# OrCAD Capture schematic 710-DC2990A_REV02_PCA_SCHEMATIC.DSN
size B; title: 5V, 3A SYNCHRONOUS STEP-DOWN SILENT SWITCHER; rev: 01
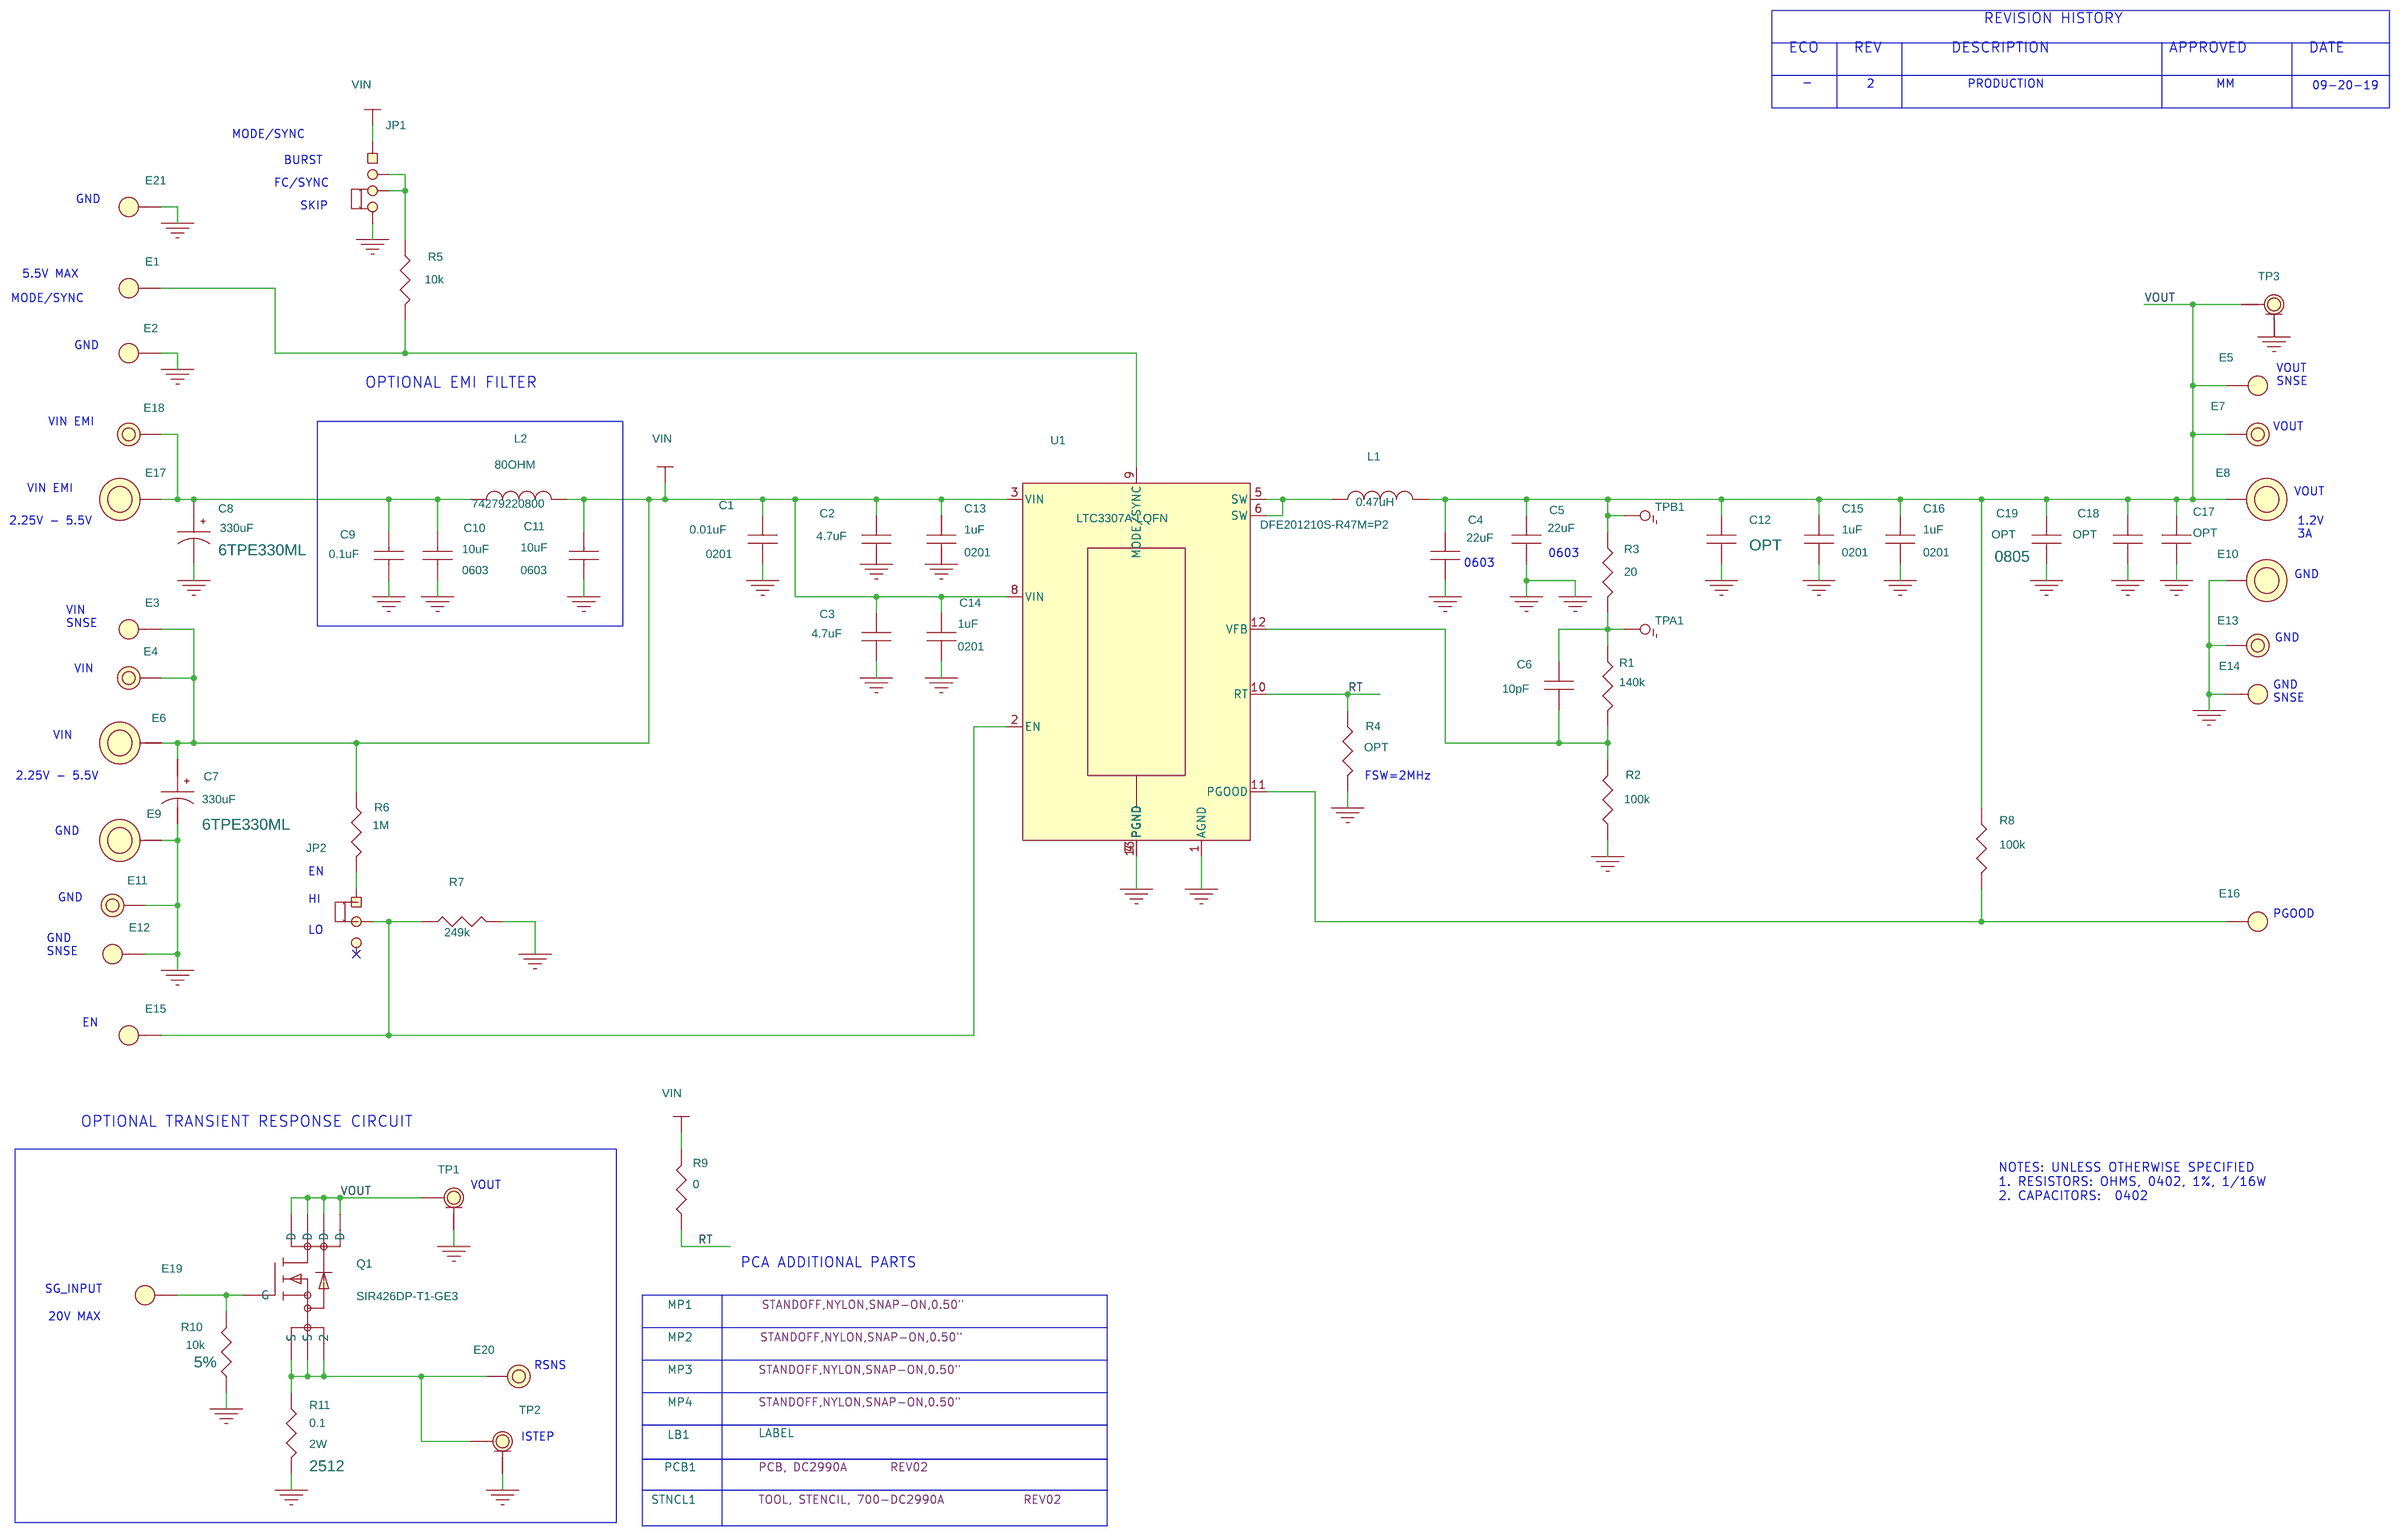
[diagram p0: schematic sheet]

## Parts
C1  0.01uF  [CC0201M]
C2  4.7uF  [CC0402N]
C3  4.7uF  [CC0402N]
C4  22uF  [CC0603N]
C5  22uF  [CC0603N]
C6  10pF  [CC0402N]
C7  330uF  [CAPMP7343N]
C8  330uF  [CAPMP7343N]
C9  0.1uF  [CC0402N]
C10  10uF  [CC0603N]
C11  10uF  [CC0603N]
C12  0.1uF  [CC0402N]
C13  1uF  [CC0201M]
C14  1uF  [CC0201M]
C15  1uF  [CC0201M]
C16  1uF  [CC0201M]
C17  OPT  [CC0402N]
C18  OPT  [CC0805N]
C19  OPT  [CC0805N]
E1  TEST POINT  [MILLMAX2308]
E2  TEST POINT  [MILLMAX2308]
E3  TEST POINT  [MILLMAX2308]
E4  TEST POINT  [MILLMAX2501]
E5  TEST POINT  [MILLMAX2308]
E6  BANANA JACK  [KEY-575-4]
E7  TEST POINT  [MILLMAX2501]
E8  BANANA JACK  [KEY-575-4]
E9  BANANA JACK  [KEY-575-4]
E10  BANANA JACK  [KEY-575-4]
E11  TEST POINT  [MILLMAX2501]
E12  TEST POINT  [MILLMAX2308]
E13  TEST POINT  [MILLMAX2501]
E14  TEST POINT  [MILLMAX2308]
E15  TEST POINT  [MILLMAX2308]
E16  TEST POINT  [MILLMAX2308]
E17  BANANA JACK  [KEY-575-4]
E18  TEST POINT  [MILLMAX2501]
E19  TEST POINT  [MILLMAX2308]
E20  TEST POINT  [MILLMAX2501]
E21  TEST POINT  [MILLMAX2308]
JP1  HDR  [JP4X1/079]
JP2  HDR  [HD1X3-079]
L1  0.47uH  [MURATA-DFE201210S]
L2  80OHM  [WURTH-0805]
LB1  LABEL  [895-0154_REV01]
MP1  STANDOFF  [KEYSTONE_8829-8834]
MP2  STANDOFF  [KEYSTONE_8829-8834]
MP3  STANDOFF  [KEYSTONE_8829-8834]
MP4  STANDOFF  [KEYSTONE_8829-8834]
PCB1  PCB, DC2990A
Q1  SIR426DP-T1-GE3  [VISHAY_PPAK_SO-8]
R1  140k  [CR0402N]
R2  100k  [CR0402N]
R3  20  [CR0402N]
R4  OPT  [CR0402N]
R5  10k  [CR0402N]
R6  1M  [CR0402N]
R7  249k  [CR0402N]
R8  100k  [CR0402N]
R9  0  [CR0402N]
R10  10k  [CR0402N]
R11  0.1  [CR2512N]
STNCL1  TOOL, STENCIL, 700-DC2990A
TP1  U.FL  [HIROSE-FL-R-SMT-1]
TP2  TEST JACK  [HODEN-PA-652_ALT1]
TP3  U.FL  [HIROSE-FL-R-SMT-1]
TPA1  COPPER FEATURE PAD  [PADSTYLE1]
TPB1  COPPER FEATURE PAD  [PADSTYLE1]
U1  LTC3307A-LQFN  [LTC-LQFN-12-1530]
XJP1  SHUNT
XJP2  SHUNT

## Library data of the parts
C1 = CAP: CAP.,0.01uF,X7R,10V,10%,0201; CLASS: DISCRETE; Dielectric Type: X7R; FPLIST: CC0201N,CC0201L,CC0201M; Inventory Qty: 28511; Manufacturer: MURATA; Manufacturer PN: GRM033R70J103KA01D; PART_NUMBER: 150-0377; Package Size: 0201; Rated Voltage: 10V; Tolerance: 10%
C2 C3 = CAP: CAP.,4.7uF,X6S,6.3V,20%,0402; CLASS: DISCRETE; Dielectric Type: X6S; FPLIST: CC0402N, CC0402M,CC0402L; Inventory Qty: 0; Manufacturer: MURATA; Manufacturer PN: GRM155C80J475MEAAD; PART_NUMBER: 150-0793; Package Size: 0402; Rated Voltage: 6.3V; Temperature Coefficient: X6S; Tolerance: 20%
C4 C5 = CAP: CAP.,22uF,X6S,6.3V,20%,0603; CLASS: DISCRETE; Dielectric Type: X6S; FPLIST: CC0603N,CC0603L,CC0603M; Inventory Qty: 0; Manufacturer: MURATA; Manufacturer PN: GRM188C80J226ME15D; PART_NUMBER: 150-0784; Package Size: 0603; Rated Voltage: 6.3V; Temperature Coefficient: X6S; Tolerance: 20%
C6 = CAP: CAP.,10pF,C0G,50V,5%,0402,AEC-Q200; CLASS: DISCRETE; Dielectric Type: C0G; FPLIST: CC0402N,CC0402L,CC0402M; Inventory Qty: 23844; Manufacturer: MURATA; Manufacturer PN: GCM1555C1H100JA16D; PART_NUMBER: 150-1207; Package Size: 0402; Rated Voltage: 50V; Temperature Coefficient: C0G, NP0; Tolerance: 5%
C7 C8 = CAP_P_ALT: CAP.,330uF,TANT. POSCAP,6.3V,20%,7343,25mOHMS, TPE, NO SUBS. ALLOWED; CLASS: DISCRETE; Dielectric Type: TANT. POSCAP; Inventory Qty: 2150; Manufacturer: PANASONIC; Manufacturer PN: 6TPE330ML; PART_NUMBER: 150-0529; Package Size: 7343; Rated Voltage: 6.3V; Tolerance: 20%; UserField01: 2400mAms, 25mOHMS
C9 = CAP: CAP.,0.1uF,X7R,16V,10%,0402,AEC-Q200; CLASS: DISCRETE; Dielectric Type: X7R; FPLIST: CC0402N,CC0402L,CC0402M; Inventory Qty: 23683; Manufacturer: MURATA; Manufacturer PN: GCM155R71C104KA55D; PART_NUMBER: 150-0506; Package Size: 0402; Rated Voltage: 16V; Tolerance: 10%
C10 C11 = CAP: CAP.,10uF,X7S,6.3V,20%,0603; CLASS: DISCRETE; Dielectric Type: X7S; FPLIST: CC0603N,CC0603L,CC0603M; Inventory Qty: 10800; Manufacturer: TDK; Manufacturer PN: C1608X7S0J106M080AC; PART_NUMBER: 150-1745; Package Size: 0603; Rated Voltage: 6.3V; Tolerance: 20%
C12 = CAP: CAP.,0.1uF,X5R,25V,10%,0402; BOM Notes: OPT; CLASS: DISCRETE; Dielectric Type: X5R; FPLIST: CC0402N,CC0402L,CC0402M; Inventory Qty: 71484; Manufacturer: AVX; Manufacturer PN: 04023D104KAT2A; PART_NUMBER: 150-0249; Package Size: 0402; Rated Voltage: 25V; Tolerance: 10%
C13-C16 = CAP: CAP.,1uF,X7T,6.3V,20%,0201; CLASS: DISCRETE; Dielectric Type: X7T; FPLIST: CC0201N,CC0201L,CC0201M; Inventory Qty: 600; Manufacturer: MURATA; Manufacturer PN: GRM033D70J105ME01D; PART_NUMBER: 150-1771; Package Size: 0201; Rated Voltage: 6.3V; Tolerance: 20%
C17 = CAP: CAP., OPTION, 0402; CLASS: DISCRETE; FPLIST: CC0402N,CC0402L,CC0402M; PART_NUMBER: 150-3148; Package Size: 0402; Package Type: SMD
C18 C19 = CAP: CAP., OPTION, 0805; CLASS: DISCRETE; FPLIST: CC0805N,CC0805L,CC0805M; PART_NUMBER: 150-3036; Package Size: 0805; Package Type: SMD
E1-E3 E5 E12 E14-E16 E19 E21 = TEST_POINT_.156_MILL-MAX_2308: TEST POINT,TURRET,0.064" MTG. HOLE,PCB 0.062" THK; CLASS: IO; Inventory Qty: 760562; Manufacturer PN: 2308-2-00-80-00-00-07-0; PART_NUMBER: 260-0004
E4 E7 E11 E13 E18 E20 = TESTPOINT_.219_MILL-MAX_2501: TEST POINT,TURRET,0.094" MTG. HOLE,PCB 0.062" THK; CLASS: IO; Inventory Qty: 452838; Manufacturer: MILL-MAX; Manufacturer PN: 2501-2-00-80-00-00-07-0; PART_NUMBER: 260-0003
E6 E8-E10 E17 = BANANA_KEYSTONE-575-4: CONN.,BANANA JACK,FEMALE,THT,NON-INSULATED,SWAGE,0.218"; CLASS: IO; Inventory Qty: 194619; Manufacturer: KEYSTONE; Manufacturer PN: 575-4; PART_NUMBER: 250-0428
JP1 = HD1X4-079_ALT: CONN.,HDR,MALE,1x4,2mm,VERT,ST,THT; CLASS: IO; Inventory Qty: 10969; Manufacturer: WURTH ELEKTRONIK; Manufacturer PN: 62000411121; PART_NUMBER: 250-0563
JP2 = 3_PIN_HEADER_.079_SINGLE_ROW_D: CONN.,HDR,MALE,1x3,2mm,VERT,ST,THT; CLASS: IO; Inventory Qty: 26164; Manufacturer: Wurth Elektronik; Manufacturer PN: 62000311121; PART_NUMBER: 250-0484
L1 = IND_ALT: IND.,0.47uH,POWER,20%,3.4A,0.032OHMS,0805; CLASS: DISCRETE; Inventory Qty: 0; Manufacturer: MURATA; Manufacturer PN: DFE201210S-R47M=P2; PART_NUMBER: 200-0784; Package Size: 0805; Tolerance: 20%
L2 = IND_ALT: IND.,80OHM,FERRITE BEAD,25%,4A,0.018OHM,0805,100MHz; CLASS: DISCRETE; Inventory Qty: 0; Manufacturer: WURTH ELEKTRONIK; Manufacturer PN: 74279220800; PART_NUMBER: 200-0765; Package Size: 0805; Tolerance: 25%
LB1 = BLANK_LABEL: LABEL SPEC, DEMO BOARD SERIAL NUMBER; Inventory Qty: 0; Manufacturer: BRADY; Manufacturer PN: THT-96-717-10; PART_NUMBER: 895-0154
MP1-MP4 = BLANK_MECHANICAL_PART: STANDOFF,NYLON,SNAP-ON,0.50"; CLASS: DISCRETE; FPLIST: KEYSTONE_8829-8834,MTG-8831; Inventory Qty: 10977; Manufacturer: WURTH ELEKTRONIK; Manufacturer PN: 702935000; PART_NUMBER: 763-0020
PCB1 = BLANK_PCB_PART: BOM Notes: REV02; CLASS: DISCRETE; Inventory Qty: 0; Manufacturer: MAO BANG; Manufacturer PN: 600-DC2990A; PART_NUMBER: 600-DC2990A
Q1 = 8P_N-CH_TYPE1A: XSTR.,MOSFET,N-CH,40V,15.9A,PPAK SO-8; CLASS: DISCRETE; Inventory Qty: 14900; Manufacturer: VISHAY; PART_NUMBER: 240-0378; Package Size: PowerPAK® SO-8; Package Type: PPAK SO-8; Polarity: MOSFET N-Channel; Rated Power: 41.7W; Rated Voltage: 40V
R1 = RES: RES.,140k OHMS,1%,1/16W,0402,AEC-Q200; CLASS: DISCRETE; FPLIST: CR0402N,CR0402L,CR0402M; Inventory Qty: 72990; Manufacturer: NIC; Manufacturer PN: NRC04F1403TRF; PART_NUMBER: 100-2880; Package Size: 0402; Rated Power: 1/16W; Temperature Coefficient: 100ppm; Tolerance: 1%
R2 = RES: RES.,100k OHMS,1%,1/16W,0402,AEC-Q200; CLASS: DISCRETE; FPLIST: CR0402N,CR0402L,CR0402M; Inventory Qty: 136714; Manufacturer: VISHAY; Manufacturer PN: CRCW0402100KFKED; PART_NUMBER: 100-2396; Package Size: 0402; Rated Power: 1/16W; Temperature Coefficient: 100ppm; Tolerance: 1%
R3 = RES: RES.,20 OHMS,1%,1/16W,0402,AEC-Q200; CLASS: DISCRETE; FPLIST: CR0402N,CR0402L,CR0402M; Inventory Qty: 33808; Manufacturer: NIC; Manufacturer PN: NRC04F20R0TRF; PART_NUMBER: 100-0250; Package Size: 0402; Rated Power: 1/16W; Temperature Coefficient: 100ppm; Tolerance: 1%
R4 = RES: RES., OPTION, 0402; CLASS: DISCRETE; FPLIST: CR0402N,CR0402L,CR0402M; PART_NUMBER: 100-0357; Package Size: 0402
R5 = RES: RES.,10k OHMS,5%,1/16W,0402,AEC-Q200; CLASS: DISCRETE; FPLIST: CR0402N,CR0402L,CR0402M; Inventory Qty: 71445; Manufacturer: NIC; Manufacturer PN: NRC04J103TRF; PART_NUMBER: 100-0214; Package Size: 0402; Rated Power: 1/16W; Temperature Coefficient: 200ppm; Tolerance: 5%
R6 = RES: RES.,1M OHMS,1%,1/16W,0402,AEC-Q200; CLASS: DISCRETE; FPLIST: CR0402N,CR0402L,CR0402M; Inventory Qty: 92093; Manufacturer: STACKPOLE ELECTRONICS, INC.; Manufacturer PN: RMCF0402FT1M00; PART_NUMBER: 100-2457; Package Size: 0402; Rated Power: 1/16W; Temperature Coefficient: 100ppm; Tolerance: 1%
R7 = RES: RES.,249k OHMS,1%,1/16W,0402,AEC-Q200; CLASS: DISCRETE; FPLIST: CR0402N,CR0402L,CR0402M; Inventory Qty: 29476; Manufacturer: NIC; Manufacturer PN: NRC04F2493TRF; PART_NUMBER: 100-2663; Package Size: 0402; Rated Power: 1/16W; Temperature Coefficient: 100ppm; Tolerance: 1%
R8 = RES: RES.,100k OHMS,5%,1/16W,0402; CLASS: DISCRETE; FPLIST: CR0402N,CR0402L,CR0402M; Inventory Qty: 92947; Manufacturer: YAGEO; Manufacturer PN: RC0402JR-07100KL; PART_NUMBER: 100-0058; Package Size: 0402; Rated Power: 1/16W; Temperature Coefficient: 100ppm/C; Tolerance: 5%
R9 = RES: RES.,0 OHM,1/16W,0402; CLASS: DISCRETE; FPLIST: CR0402N,CR0402L,CR0402M; Inventory Qty: 218399; Manufacturer: ROHM; Manufacturer PN: MCR01MZPJ000; PART_NUMBER: 100-0215; Package Size: 0402; Rated Power: 1/16W
R10 = RES: RES.,10k OHMS,5%,1/10W,0402,AEC-Q200; CLASS: DISCRETE; FPLIST: CR0402N,CR0402L,CR0402M; Inventory Qty: 34711; Manufacturer: PANASONIC; Manufacturer PN: ERJ2GEJ103X; PART_NUMBER: 100-0092; Package Size: 0402; Rated Power: 1/10W; Temperature Coefficient: 200ppm/C; Tolerance: 5%
R11 = RES: RES.,0.1 OHM,1%,2W,2512,SENSE,AEC-Q200; CLASS: DISCRETE; FPLIST: CR2512N,CR2512L,CR2512M; Inventory Qty: 6840; Manufacturer: IRC; Manufacturer PN: LRC-LR2512LF-01-R100-F; PART_NUMBER: 100-0553; Package Size: 2512; Rated Power: 2W; Temperature Coefficient: 100ppm; Tolerance: 1%
STNCL1 = BLANK_STENCIL_PART: BOM Notes: REV02; CLASS: DISCRETE; Inventory Qty: 0; Manufacturer: ANALOG DEVICES; Manufacturer PN: 830-DC2990A; PART_NUMBER: 830-DC2990A
TP1 TP3 = HIROSE-U.FL-R-SMT-1: CONN.,U.FL,RECEPT,ST SMD,0Hz to 6GHz 50Ohm; CLASS: IO; Inventory Qty: 0; Manufacturer: HIROSE ELECTRIC; Manufacturer PN: U.FL-R-SMT-1(10); PART_NUMBER: 250-0939
TP2 = HODEN_TEST_JACK_PK5-2.5MM-113_1: CONN.,TEST JACK,PLUG,VERT. THT,SHIELDED, 1 POS; CLASS: IO; FPLIST: HODEN-PA-652, HODEN-PA-652_ALT1; Manufacturer: HODEN ELECTRONICS CO; Manufacturer PN: PK5-2.5MM-113; PART_NUMBER: TMP-3717
TPA1 TPB1 = PAD_SMALL_FILLED: TESTPOINT, PCB COPPER FEATURE; CLASS: IO; Manufacturer: N/A; Manufacturer PN: N/A; PART_NUMBER: PCBPADS-11
U1 = LTC3307A-LQFN: IC,5V, 3A SYNCHRONOUS STEP-DOWN SILENT SWITCHER,12-pin 2x2 LQFN; CLASS: IC; Inventory Qty: 0; Manufacturer: ANALOG DEVICES; Manufacturer PN: LTC3307AEV#PBF; PART_NUMBER: LTC3307AEV#PBF; Package Size: 12-LGA; Package Type: 12-pin 2x2 LQFN
XJP1 XJP2 = CONN_SHUNT_2_POS_2mm: CONN.,SHUNT,FEMALE,2 POS,2mm; CLASS: IO; Inventory Qty: 67158; Manufacturer: Wurth Elektronik; Manufacturer PN: 60800213421; PART_NUMBER: 250-0485

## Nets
GND: C1.2 C2.2 C3.2 C4.2 C5.2 C7.2 C8.2 C9.2 C10.2 C11.2 C12.2 C13.2 C14.2 C15.2 C16.2 C17.2 C18.2 C19.2 E2.1(A) E9.1 E10.1 E11.1 E12.1(A) E13.1 E14.1(A) E21.1(A) JP1.4 R2.1 R4.2 R7.2 R10.2 R11.2 TP1.2(GND) TP1.3(GND) TP1.4(GND) TP1.5(GND) TP2.2(GND) TP2.3(GND) TP2.4(GND) TP2.5(GND) TP3.2(GND) TP3.3(GND) U1.1(AGND) U1.4(PGND) U1.7(PGND) U1.13(PGND)
VIN: C1.1 C2.1 C3.1 C7.1 C11.1 C13.1 C14.1 E3.1(A) E4.1 E6.1 JP1.1 L2.2 R6.1 R9.2 U1.3(VIN) U1.8(VIN)
RT: R4.1 R9.1 U1.10(RT)
VOUT: C4.1 C5.1 C12.1 C15.1 C16.1 C17.1 C18.1 C19.1 E5.1(A) E7.1 E8.1 L1.2 Q1.5(D) Q1.6(D) Q1.7(D) Q1.8(D) R3.1 R8.1 TP1.1 TP3.1 TPB1.1
N16763174: L1.1 U1.5(SW) U1.6(SW)
N16763234: C6.2 R1.2 R2.2 U1.12(VFB)
N16763242: E15.1(A) JP2.2 R7.1 U1.2(EN)
N16763412: C6.1 R1.1 R3.2 TPA1.1
N16763484: E16.1(A) R8.2 U1.11(PGOOD)
N16763862: JP2.1 R6.2
N16780618: JP1.2 JP1.3 R5.1
N16781465: E1.1(A) R5.2 U1.9(MODE/SYNC)
N16886451: C8.1 C9.1 C10.1 E17.1 E18.1 L2.1
N16894176: E20.1 Q1.1(S) Q1.2(S) Q1.3(2) R11.1 TP2.1
N16918546: E19.1(A) Q1.4(G) R10.1

Not connected (* = marked no-connect by the designer): JP2 3*; TP3 4(GND) 5(GND)

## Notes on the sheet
- REVISION HISTORY
- ECO
- REV
- DESCRIPTION
- APPROVED
- DATE
- -
- 2
- PRODUCTION
- MM
- 09-20-19
- MODE/SYNC
- BURST
- GND
- FC/SYNC
- SKIP
- 5.5V MAX
- MODE/SYNC
- GND
- VOUT
  SNSE
- OPTIONAL EMI FILTER
- VIN EMI
- VOUT
- VIN EMI
- VOUT
- 2.25V - 5.5V
- 1.2V
  3A
- 0603
- 0603
- GND
- VIN
  SNSE
- GND
- VIN
- GND
  SNSE
- VIN
- 2.25V - 5.5V
- FSW=2MHz
- GND
- EN
- GND
- HI
- PGOOD
- GND
  SNSE
- LO
- EN
- OPTIONAL TRANSIENT RESPONSE CIRCUIT
- NOTES: UNLESS OTHERWISE SPECIFIED
  1. RESISTORS: OHMS, 0402, 1%, 1/16W
  2. CAPACITORS:  0402
- VOUT
- PCA ADDITIONAL PARTS
- SG_INPUT
- 20V MAX
- RSNS
- ISTEP
